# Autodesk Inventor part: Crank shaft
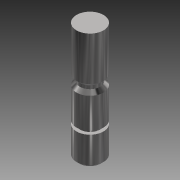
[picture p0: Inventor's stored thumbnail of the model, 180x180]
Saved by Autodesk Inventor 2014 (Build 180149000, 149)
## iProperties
Created: 2008-06
Part Number: Crank shaft
Document SubType Name: Modeling
Designer: tangg
Density: 7.84 g/cm^3
Mass: 5.33262 g
Surface Area: 21.043 cm^2
Volume: 5.33262 cm^3
Material: Steel, High Strength Low Alloy
Appearance: Steel - Polished
Author: tangg
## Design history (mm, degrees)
sketch "Sketch8"
  geometry: C1 r 6.35 at (0, 0) reference; 1 further point
extrude "Extrusion4" new body sketch "Sketch8" distance "d13" = 55; taper "d14" = 0 deg
chamfer "Chamfer2" distance "d15" = 1.27; stored, may be unused: second distance "d16" = 3.175, angle "d17" = 45 deg
sketch "Sketch9"
  geometry: L1 (-6.35, 0)-(-6.35, -53.73) reference; L2 (-4.763, -22.225)-(-4.763, -23.812); L3 (-6.35, -25.4)-(-6.35, -20.637); L4 (-6.35, -41.275)-(-4.763, -41.275); L5 (-4.763, -41.275)-(-4.763, -39.688); L6 (-4.763, -39.688)-(-6.35, -39.688); L7 (-6.35, -39.688)-(-6.35, -41.275); L8 (0, -64.476)-(0, 10.746) reference; L9 (-4.763, -22.225)-(-6.35, -20.637); L10 (-4.763, -23.812)-(-6.35, -25.4); 1 further point
  constraints: 16 end point, 3 point on line
revolve "Revolution1" sketch "Sketch9" stored, may be unused: angle "d18" = 90 deg
body "Solid1"
